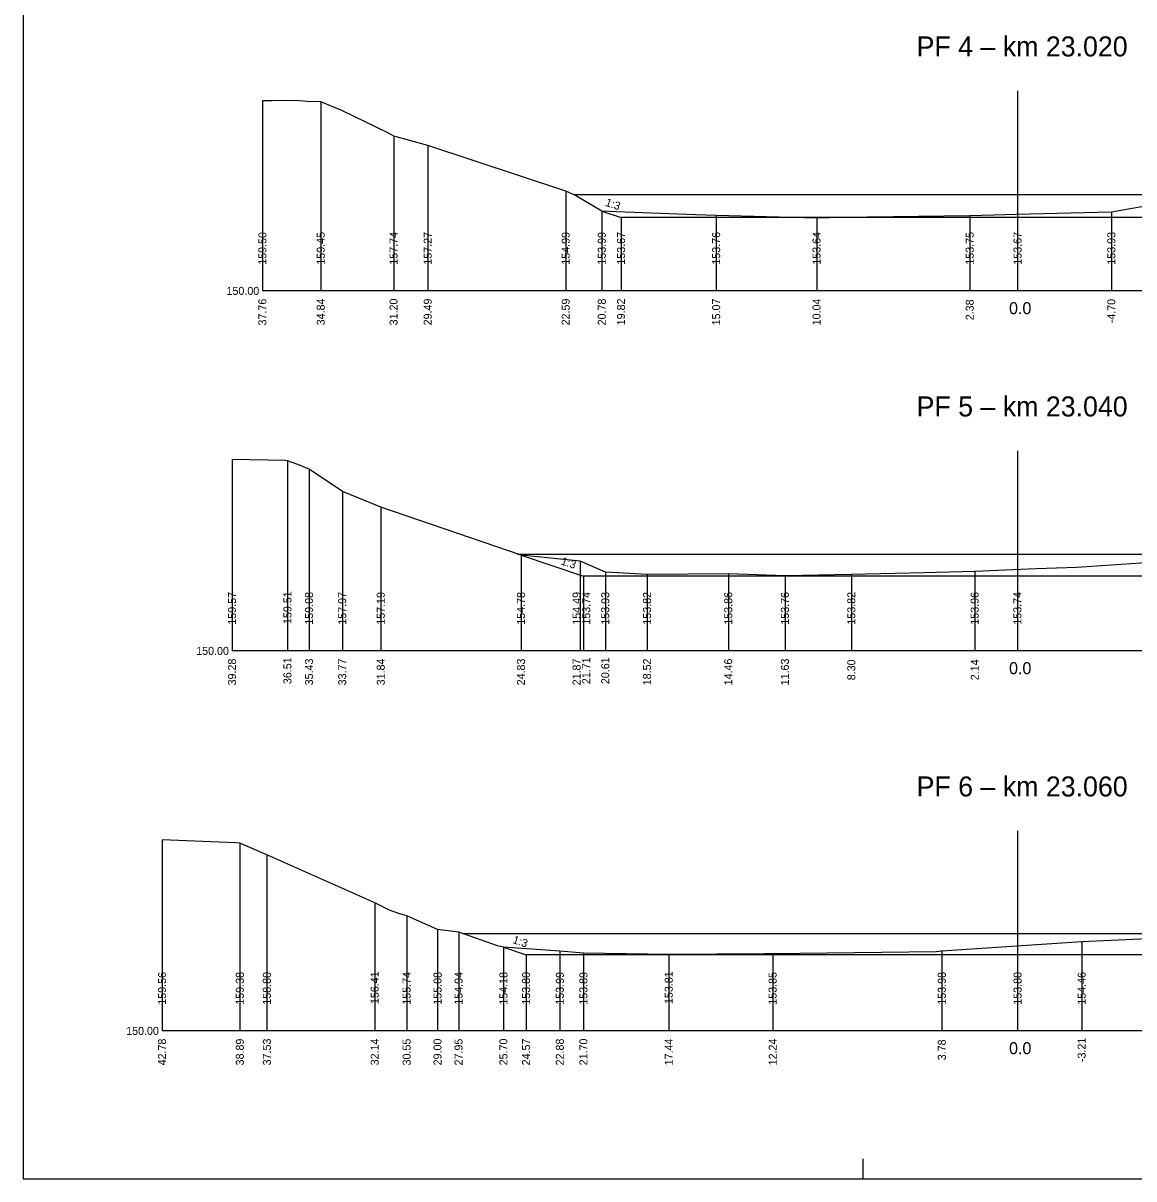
# Model space of a CAD drawing. Extents: x -582678 to -581845, y -1210354 to -1210235.
# Drawn here: x -582677.5 to -582622, y -1210354.1 to -1210296.3 of the extents above; entities that cross this region are included whole.
import ezdxf

# ---------------------------------------------------------------- set-up
doc = ezdxf.new("R2010")
doc.units = 0
for name, color, linetype in [('_N_osa', 7, 'Continuous'), ('_N_popis', 7, 'Continuous'), ('_N_tučná', 7, 'Continuous'), ('_rámeček', 7, 'Continuous'), ('_S_hladina', 7, 'Continuous'), ('_S_popis', 7, 'Continuous'), ('_S_popis_oprav!', 7, 'Continuous'), ('_S_tenká', 7, 'Continuous'), ('_S_velmi_tenká', 7, 'Continuous')]:
    doc.layers.add(name, color=color, linetype=linetype)

msp = doc.modelspace()

# ---------------------------------------------------------------- linework, layer by layer
at = {"layer": '_N_osa'}
for p, q in [((-582627.772, -1210299.691), (-582627.772, -1210309.691)), ((-582627.772, -1210317.691), (-582627.772, -1210327.691)), ((-582627.772, -1210336.691), (-582627.772, -1210346.691))]:
    msp.add_line(p, q, dxfattribs=at)
at = {"layer": '_N_popis'}
for points in [[(-582648.556, -1210305.7), (-582648.556, -1210309.691), (-582648.556, -1210309.691), (-582648.556, -1210309.691)], [(-582647.594, -1210306.021), (-582647.594, -1210309.691), (-582647.594, -1210309.691), (-582647.594, -1210309.691)], [(-582652.599, -1210322.913), (-582652.599, -1210327.691), (-582652.599, -1210327.691), (-582652.599, -1210327.691)], [(-582649.48, -1210323.951), (-582649.48, -1210327.691), (-582649.48, -1210327.691), (-582649.48, -1210327.691)], [(-582653.475, -1210342.513), (-582653.475, -1210346.691), (-582653.475, -1210346.691), (-582653.475, -1210346.691)], [(-582652.343, -1210342.891), (-582652.343, -1210346.691), (-582652.343, -1210346.691), (-582652.343, -1210346.691)]]:
    msp.add_lwpolyline(points, dxfattribs=at)
at = {"layer": '_N_tučná'}
for p, q in [((-582648.556, -1210305.7), (-582647.594, -1210306.021)), ((-582652.599, -1210322.911), (-582649.48, -1210323.951)), ((-582653.475, -1210342.513), (-582652.343, -1210342.891))]:
    msp.add_line(p, q, dxfattribs=at)
for points in [[(-582603.128, -1210306.021), (-582647.594, -1210306.021)], [(-582603.264, -1210323.951), (-582649.48, -1210323.951)], [(-582597.016, -1210342.891), (-582652.343, -1210342.891)]]:
    msp.add_lwpolyline(points, dxfattribs=at)
at = {"layer": '_rámeček'}
for p, q in [((-582677.502, -1210235.291), (-582677.502, -1210354.091)), ((-582635.502, -1210353.091), (-582635.502, -1210354.091)), ((-582677.502, -1210354.091), (-582467.502, -1210354.091))]:
    msp.add_line(p, q, dxfattribs=at)
at = {"layer": '_S_hladina'}
for points in [[(-582649.957, -1210304.881), (-582600.057, -1210304.881)], [(-582652.78, -1210322.851), (-582600.971, -1210322.851)], [(-582655.532, -1210341.821), (-582594.384, -1210341.821)]]:
    msp.add_lwpolyline(points, dxfattribs=at)
at = {"layer": '_S_popis'}
msp.add_lwpolyline([(-582648.385, -1210323.757), (-582648.385, -1210327.691), (-582648.385, -1210327.691), (-582648.385, -1210327.691)], dxfattribs=at)
at = {"layer": '_S_tenká'}
for p, q in [((-582581.245, -1210309.691), (-582665.531, -1210309.691)), ((-582579.618, -1210327.691), (-582667.048, -1210327.691)), ((-582577.772, -1210346.691), (-582670.549, -1210346.691))]:
    msp.add_line(p, q, dxfattribs=at)
for points in [[(-582621.376, -1210305.448), (-582623.076, -1210305.756), (-582627.844, -1210305.87), (-582628.955, -1210305.911), (-582630.156, -1210305.943), (-582636.559, -1210306.026), (-582637.817, -1210306.05), (-582642.837, -1210305.928), (-582643.882, -1210305.892), (-582647.833, -1210305.738), (-582648.556, -1210305.7), (-582649.916, -1210304.899), (-582650.361, -1210304.704), (-582657.262, -1210302.416), (-582658.97, -1210301.952), (-582659.236, -1210301.8), (-582661.57, -1210300.674), (-582662.611, -1210300.239), (-582662.671, -1210300.242), (-582663.32, -1210300.223), (-582663.884, -1210300.17), (-582665.039, -1210300.187), (-582665.531, -1210300.192)], [(-582620.872, -1210323.248), (-582624.812, -1210323.519), (-582626.833, -1210323.592), (-582629.911, -1210323.73), (-582632.451, -1210323.797), (-582636.077, -1210323.871), (-582639.399, -1210323.934), (-582642.232, -1210323.835), (-582646.292, -1210323.87), (-582648.385, -1210323.757), (-582649.641, -1210323.198), (-582652.599, -1210322.913), (-582659.61, -1210320.501), (-582661.538, -1210319.718), (-582663.198, -1210318.612), (-582663.325, -1210318.558), (-582663.63, -1210318.425), (-582664.277, -1210318.186), (-582664.399, -1210318.18), (-582667.048, -1210318.121)], [(-582619.807, -1210342.023), (-582624.559, -1210342.231), (-582631.552, -1210342.712), (-582631.823, -1210342.731), (-582631.835, -1210342.731), (-582640.014, -1210342.842), (-582640.424, -1210342.846), (-582645.211, -1210342.879), (-582649.477, -1210342.799), (-582650.656, -1210342.698), (-582653.475, -1210342.513), (-582653.779, -1210342.435), (-582655.72, -1210341.755), (-582656.771, -1210341.614), (-582658.318, -1210340.947), (-582658.664, -1210340.841), (-582659.149, -1210340.665), (-582659.915, -1210340.282), (-582665.306, -1210337.893), (-582666.658, -1210337.312), (-582666.879, -1210337.295), (-582670.549, -1210337.136)]]:
    msp.add_lwpolyline(points, dxfattribs=at)
at = {"layer": '_S_velmi_tenká'}
for points in [[(-582665.531, -1210300.192), (-582665.531, -1210309.696), (-582665.531, -1210309.696), (-582665.531, -1210309.696)], [(-582662.611, -1210300.239), (-582662.611, -1210309.691), (-582662.611, -1210309.691), (-582662.611, -1210309.691)], [(-582658.97, -1210301.952), (-582658.97, -1210309.691), (-582658.97, -1210309.691), (-582658.97, -1210309.691)], [(-582657.262, -1210302.416), (-582657.262, -1210309.691), (-582657.262, -1210309.691), (-582657.262, -1210309.691)], [(-582650.361, -1210304.704), (-582650.361, -1210309.691), (-582650.361, -1210309.691), (-582650.361, -1210309.691)], [(-582642.837, -1210305.928), (-582642.837, -1210309.691), (-582642.837, -1210309.691), (-582642.837, -1210309.691)], [(-582630.156, -1210305.943), (-582630.156, -1210309.691), (-582630.156, -1210309.691), (-582630.156, -1210309.691)], [(-582623.076, -1210305.756), (-582623.076, -1210309.691), (-582623.076, -1210309.691), (-582623.076, -1210309.691)], [(-582637.817, -1210306.05), (-582637.817, -1210309.691), (-582637.817, -1210309.691), (-582637.817, -1210309.691)], [(-582667.048, -1210318.121), (-582667.048, -1210327.691), (-582667.048, -1210327.691), (-582667.048, -1210327.691)], [(-582664.277, -1210318.186), (-582664.277, -1210327.691), (-582664.277, -1210327.691), (-582664.277, -1210327.691)], [(-582663.198, -1210318.612), (-582663.198, -1210327.691), (-582663.198, -1210327.691), (-582663.198, -1210327.691)], [(-582661.538, -1210319.718), (-582661.538, -1210327.691), (-582661.538, -1210327.691), (-582661.538, -1210327.691)], [(-582659.61, -1210320.501), (-582659.61, -1210327.691), (-582659.61, -1210327.691), (-582659.61, -1210327.691)], [(-582649.641, -1210323.198), (-582649.641, -1210327.691), (-582649.641, -1210327.691), (-582649.641, -1210327.691)], [(-582646.292, -1210323.87), (-582646.292, -1210327.691), (-582646.292, -1210327.691), (-582646.292, -1210327.691)], [(-582642.232, -1210323.835), (-582642.232, -1210327.691), (-582642.232, -1210327.691), (-582642.232, -1210327.691)], [(-582639.399, -1210323.934), (-582639.399, -1210327.691), (-582639.399, -1210327.691), (-582639.399, -1210327.691)], [(-582636.077, -1210323.871), (-582636.077, -1210327.691), (-582636.077, -1210327.691), (-582636.077, -1210327.691)], [(-582629.911, -1210323.73), (-582629.911, -1210327.691), (-582629.911, -1210327.691), (-582629.911, -1210327.691)], [(-582670.549, -1210337.136), (-582670.549, -1210346.691), (-582670.549, -1210346.691), (-582670.549, -1210346.691)], [(-582666.658, -1210337.312), (-582666.658, -1210346.691), (-582666.658, -1210346.691), (-582666.658, -1210346.691)], [(-582665.306, -1210337.893), (-582665.306, -1210346.691), (-582665.306, -1210346.691), (-582665.306, -1210346.691)], [(-582659.915, -1210340.282), (-582659.915, -1210346.691), (-582659.915, -1210346.691), (-582659.915, -1210346.691)], [(-582658.318, -1210340.947), (-582658.318, -1210346.691), (-582658.318, -1210346.691), (-582658.318, -1210346.691)], [(-582656.771, -1210341.614), (-582656.771, -1210346.691), (-582656.771, -1210346.691), (-582656.771, -1210346.691)], [(-582655.72, -1210341.755), (-582655.72, -1210346.691), (-582655.72, -1210346.691), (-582655.72, -1210346.691)], [(-582624.559, -1210342.231), (-582624.559, -1210346.691), (-582624.559, -1210346.691), (-582624.559, -1210346.691)], [(-582650.656, -1210342.698), (-582650.656, -1210346.691), (-582650.656, -1210346.691), (-582650.656, -1210346.691)], [(-582649.477, -1210342.799), (-582649.477, -1210346.691), (-582649.477, -1210346.691), (-582649.477, -1210346.691)], [(-582645.211, -1210342.879), (-582645.211, -1210346.691), (-582645.211, -1210346.691), (-582645.211, -1210346.691)], [(-582640.014, -1210342.842), (-582640.014, -1210346.691), (-582640.014, -1210346.691), (-582640.014, -1210346.691)], [(-582631.552, -1210342.712), (-582631.552, -1210346.691), (-582631.552, -1210346.691), (-582631.552, -1210346.691)]]:
    msp.add_lwpolyline(points, dxfattribs=at)

# ---------------------------------------------------------------- texts
at = {"layer": '_N_popis'}
for s, height, rotation, p in [('1:3', 0.4, 341.56505, (-582648.418, -1210305.428)), ('153.99', 0.4, 90, (-582648.363, -1210308.382)), ('153.67', 0.4, 90, (-582647.401, -1210308.381)), ('153.67', 0.4, 90, (-582627.572, -1210308.381)), ('20.78', 0.4, 90, (-582648.363, -1210311.417)), ('19.82', 0.4, 90, (-582647.401, -1210311.413)), ('0.0', 0.6, 360, (-582628.196, -1210310.856)), ('1:3', 0.4, 341.56505, (-582650.634, -1210323.362)), ('154.78', 0.4, 90, (-582652.406, -1210326.382)), ('153.74', 0.4, 90, (-582649.14, -1210326.381)), ('153.74', 0.4, 90, (-582627.579, -1210326.381)), ('24.83', 0.4, 90, (-582652.406, -1210329.416)), ('21.71', 0.4, 90, (-582649.14, -1210329.353)), ('0.0', 0.6, 360, (-582628.196, -1210328.856)), ('1:3', 0.4, 341.56505, (-582653.05, -1210342.295)), ('154.18', 0.4, 90, (-582653.282, -1210345.382)), ('153.80', 0.4, 90, (-582652.149, -1210345.381)), ('153.80', 0.4, 90, (-582627.572, -1210345.381)), ('25.70', 0.4, 90, (-582653.282, -1210348.415)), ('24.57', 0.4, 90, (-582652.149, -1210348.416)), ('0.0', 0.6, 360, (-582628.196, -1210347.856))]:
    msp.add_text(s, height=height, rotation=rotation, dxfattribs=at).set_placement(p)
at = {"layer": '_S_popis'}
for s, p in [('159.50', (-582665.337, -1210308.386)), ('159.45', (-582662.418, -1210308.382)), ('157.74', (-582658.777, -1210308.381)), ('157.27', (-582657.069, -1210308.381)), ('154.99', (-582650.168, -1210308.382)), ('153.76', (-582642.644, -1210308.381)), ('153.64', (-582637.624, -1210308.381)), ('153.75', (-582629.963, -1210308.382)), ('153.93', (-582622.883, -1210308.381)), ('37.76', (-582665.337, -1210311.421)), ('34.84', (-582662.418, -1210311.415)), ('31.20', (-582658.777, -1210311.415)), ('29.49', (-582657.069, -1210311.417)), ('22.59', (-582650.168, -1210311.417)), ('15.07', (-582642.644, -1210311.416)), ('10.04', (-582637.624, -1210311.415)), ('2.38', (-582629.963, -1210311.162)), ('-4.70', (-582622.883, -1210311.313)), ('159.57', (-582666.855, -1210326.381)), ('159.51', (-582664.084, -1210326.349)), ('159.08', (-582663.005, -1210326.382)), ('157.97', (-582661.344, -1210326.381)), ('157.19', (-582659.417, -1210326.382)), ('154.49', (-582649.624, -1210326.382)), ('153.93', (-582648.191, -1210326.381)), ('153.82', (-582646.099, -1210326.38)), ('153.86', (-582642.039, -1210326.381)), ('153.76', (-582639.206, -1210326.381)), ('153.82', (-582635.884, -1210326.38)), ('153.96', (-582629.718, -1210326.381)), ('39.28', (-582666.855, -1210329.417)), ('36.51', (-582664.084, -1210329.353)), ('35.43', (-582663.005, -1210329.416)), ('33.77', (-582661.344, -1210329.416)), ('31.84', (-582659.417, -1210329.415)), ('21.87', (-582649.624, -1210329.416)), ('20.61', (-582648.191, -1210329.353)), ('18.52', (-582646.099, -1210329.413)), ('14.46', (-582642.039, -1210329.416)), ('11.63', (-582639.206, -1210329.416)), ('8.30', (-582635.884, -1210329.16)), ('2.14', (-582629.711, -1210329.16)), ('159.56', (-582670.355, -1210345.381)), ('159.38', (-582666.465, -1210345.382)), ('158.80', (-582665.113, -1210345.381)), ('156.41', (-582659.722, -1210345.349)), ('155.74', (-582658.124, -1210345.381)), ('155.08', (-582656.578, -1210345.382)), ('154.94', (-582655.527, -1210345.381)), ('153.99', (-582650.462, -1210345.382)), ('153.89', (-582649.283, -1210345.382)), ('153.81', (-582645.017, -1210345.349)), ('153.85', (-582639.821, -1210345.382)), ('153.98', (-582631.359, -1210345.382)), ('154.46', (-582624.366, -1210345.381)), ('-3.21', (-582624.366, -1210348.251)), ('42.78', (-582670.355, -1210348.417)), ('38.89', (-582666.465, -1210348.417)), ('37.53', (-582665.113, -1210348.416)), ('32.14', (-582659.722, -1210348.415)), ('30.55', (-582658.124, -1210348.419)), ('29.00', (-582656.578, -1210348.415)), ('27.95', (-582655.527, -1210348.419)), ('22.88', (-582650.462, -1210348.417)), ('21.70', (-582649.283, -1210348.415)), ('17.44', (-582645.011, -1210348.415)), ('12.24', (-582639.814, -1210348.415)), ('3.78', (-582631.359, -1210348.162))]:
    msp.add_text(s, height=0.4, rotation=90, dxfattribs=at).set_placement(p)
for p in [(-582667.33, -1210309.891), (-582668.847, -1210327.891), (-582672.348, -1210346.891)]:
    msp.add_text('150.00', height=0.4, dxfattribs=at).set_placement(p)
at = {"layer": '_S_popis_oprav!'}
for s, p in [('PF 4 – km 23.020', (-582632.82, -1210297.97)), ('PF 5 – km 23.040', (-582632.82, -1210315.97)), ('PF 6 – km 23.060', (-582632.82, -1210334.97))]:
    msp.add_text(s, height=1, dxfattribs=at).set_placement(p)

doc.saveas('drawing.dxf')
